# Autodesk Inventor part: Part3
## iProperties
Shininess: 64.0
Length Units: 11269
Angle Units: 11279
Time Units: 11290
Mass Units: 11283
Length Display Precision: 3
Angle Display Precision: 2
Compacted: True
Part Number: Part3
Document SubType Name: Modeling
Created: 2002-12
Designer: deepak
Density: 0.0
Volumn: 0.0
Area: 0.0
PropertySet Name: Model Information
Control State: 0
Master: False
Checked Out: False
Author: deepak
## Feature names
1. Sweep1
